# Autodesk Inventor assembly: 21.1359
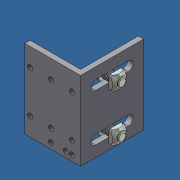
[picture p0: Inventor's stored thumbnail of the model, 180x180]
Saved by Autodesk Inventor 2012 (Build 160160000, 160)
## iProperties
Created: 2007-05
Part Number: 21.1359
Document SubType Name: Assembly
Designer: Andy Moles
Description: ANGLE BRACKET FOR SECURITY SWITCH
Author: Andy Moles
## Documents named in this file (4)
- C:\Andys Backup Data\ANDY'S INVENTOR\INVENTOR LIBRARIES\PARTS LIBRARY\ELECTRICAL INSTALLATION\21.1359 ANGLE BRACKET FOR SECURITY SWITCH.iam
- C:\Andys Backup Data\ANDY'S INVENTOR\INVENTOR LIBRARIES\PARTS LIBRARY\ELECTRICAL INSTALLATION\SUBCOMPONENTS\21.1359 ANGLE BRACKET FOR SECURITY SWITCH.ipt
- C:\Andys Backup Data\ANDY'S INVENTOR\INVENTOR LIBRARIES\PARTS LIBRARY\FASTENING ELEMENTS\SCREWS CAP\21.1200 M8X16.ipt
- C:\Andys Backup Data\ANDY'S INVENTOR\INVENTOR LIBRARIES\PARTS LIBRARY\FASTENING ELEMENTS\NUTS\21.1351 M8 SQUARE NUT.ipt
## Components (5 placed, 3 different names)
1. 21.1359 ANGLE BRACKET FOR SECURITY SWITCH:1 — Flush:1, Mate:1, Mate:2, Mate:4, Mate:7, Mate:11, Mate:12, Angle:1, Angle:2, Mate:13, Tangent:1, Mate:14, Tangent:2
2. 21.1200 M8 x 16:1 — Mate:4, Mate:9, Mate:14, Tangent:2
3. 21.1200 M8 x 16:2 — Mate:7, Mate:10, Mate:13, Tangent:1
4. 21.1351 M8 SQUARE NUT:1 — Mate:9, Mate:12, Angle:2
5. 21.1351 M8 SQUARE NUT:2 — Mate:10, Mate:11, Angle:1
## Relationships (15: Mate 10, Angle 2, Tangent 2, Flush 1)
- Flush:1: 21.1359 ANGLE BRACKET FOR SECURITY SWITCH:1
- Mate:1: 21.1359 ANGLE BRACKET FOR SECURITY SWITCH:1
- Mate:2: 21.1359 ANGLE BRACKET FOR SECURITY SWITCH:1
- Mate:4: 21.1359 ANGLE BRACKET FOR SECURITY SWITCH:1 ↔ 21.1200 M8 x 16:1
- Mate:7: 21.1359 ANGLE BRACKET FOR SECURITY SWITCH:1 ↔ 21.1200 M8 x 16:2
- Mate:9: 21.1200 M8 x 16:1 ↔ 21.1351 M8 SQUARE NUT:1
- Mate:10: 21.1200 M8 x 16:2 ↔ 21.1351 M8 SQUARE NUT:2
- Mate:11: 21.1359 ANGLE BRACKET FOR SECURITY SWITCH:1 ↔ 21.1351 M8 SQUARE NUT:2
- Mate:12: 21.1359 ANGLE BRACKET FOR SECURITY SWITCH:1 ↔ 21.1351 M8 SQUARE NUT:1
- Angle:1: 21.1359 ANGLE BRACKET FOR SECURITY SWITCH:1 ↔ 21.1351 M8 SQUARE NUT:2
- Angle:2: 21.1359 ANGLE BRACKET FOR SECURITY SWITCH:1 ↔ 21.1351 M8 SQUARE NUT:1
- Mate:13: 21.1359 ANGLE BRACKET FOR SECURITY SWITCH:1 ↔ 21.1200 M8 x 16:2
- Tangent:1: 21.1359 ANGLE BRACKET FOR SECURITY SWITCH:1 ↔ 21.1200 M8 x 16:2
- Mate:14: 21.1359 ANGLE BRACKET FOR SECURITY SWITCH:1 ↔ 21.1200 M8 x 16:1
- Tangent:2: 21.1359 ANGLE BRACKET FOR SECURITY SWITCH:1 ↔ 21.1200 M8 x 16:1
